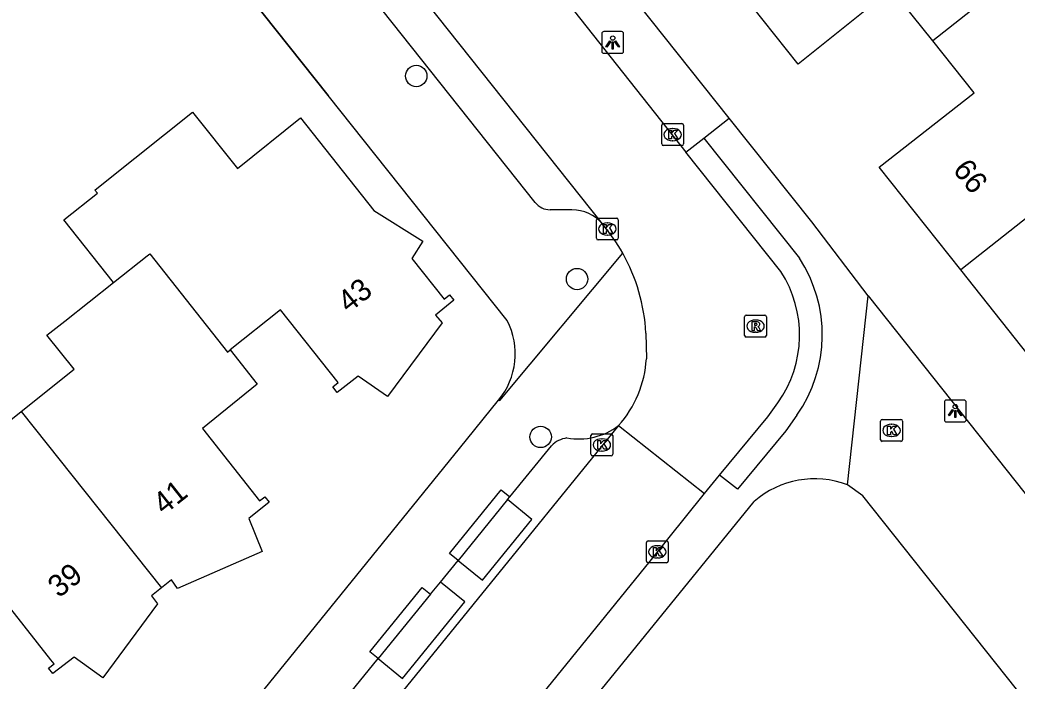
# Model space of a CAD drawing. Extents: x 157321 to 158827, y 386650 to 388532.
# Drawn here: x 157807.56 to 157853.16, y 387398.91 to 387429.15 of the extents above; entities that cross this region are included whole.
import ezdxf

# ---------------------------------------------------------------- set-up
doc = ezdxf.new("R2010")
doc.units = 0
for name, color, linetype in [('IMGEO_Boom', 7, 'Continuous'), ('IMGEO_Kolk', 7, 'Continuous'), ('IMGEO_Lichtpunt', 7, 'Continuous'), ('IMGEO_Muur', 7, 'Continuous'), ('IMGEO_Pand', 7, 'Continuous'), ('IMGEO_Pand_nummerreeks', 7, 'Continuous'), ('IMGEO_Rijbaan_lokaal_open', 7, 'Continuous'), ('IMGEO_Rioolput', 7, 'Continuous'), ('IMGEO_Voetpad_open', 7, 'Continuous')]:
    doc.layers.add(name, color=color, linetype=linetype)

msp = doc.modelspace()

# ---------------------------------------------------------------- linework, layer by layer
at = {"layer": 'IMGEO_Boom'}
for centre in [(157825.685, 387426.585), (157833.038, 387417.298), (157831.374, 387410.08)]:
    msp.add_circle(centre, 0.489, dxfattribs=at)
at = {"layer": 'IMGEO_Kolk'}
for p, q in [((157836.984, 387424.405), (157837.836, 387424.405)), ((157836.909, 387423.479), (157836.909, 387424.331)), ((157837.397, 387424.185), (157837.422, 387424.185)), ((157837.91, 387424.331), (157837.91, 387423.479)), ((157837.42, 387423.625), (157837.395, 387423.625)), ((157837.836, 387423.405), (157836.984, 387423.405)), ((157833.925, 387419.161), (157833.925, 387420.013)), ((157834, 387420.087), (157834.852, 387420.087)), ((157834.413, 387419.867), (157834.438, 387419.867)), ((157834.926, 387420.013), (157834.926, 387419.161)), ((157834.852, 387419.087), (157834, 387419.087)), ((157834.436, 387419.307), (157834.411, 387419.307)), ((157846.92, 387409.951), (157846.92, 387410.803)), ((157846.995, 387410.877), (157847.847, 387410.877)), ((157847.921, 387410.803), (157847.921, 387409.951)), ((157847.408, 387410.657), (157847.433, 387410.657)), ((157833.673, 387409.287), (157833.673, 387410.139)), ((157833.748, 387410.213), (157834.6, 387410.213)), ((157834.161, 387409.993), (157834.186, 387409.993)), ((157834.674, 387410.139), (157834.674, 387409.287)), ((157847.847, 387409.877), (157846.995, 387409.877)), ((157847.431, 387410.097), (157847.406, 387410.097)), ((157834.184, 387409.433), (157834.159, 387409.433)), ((157834.6, 387409.213), (157833.748, 387409.213)), ((157836.209, 387404.396), (157836.209, 387405.248)), ((157836.284, 387405.322), (157837.136, 387405.322)), ((157837.21, 387405.248), (157837.21, 387404.396)), ((157836.697, 387405.102), (157836.722, 387405.102)), ((157837.136, 387404.322), (157836.284, 387404.322)), ((157836.72, 387404.542), (157836.695, 387404.542))]:
    msp.add_line(p, q, dxfattribs=at)
for points in [[(157836.984, 387424.405), (157837.836, 387424.405)], [(157836.909, 387423.479), (157836.909, 387424.331)], [(157837.23, 387424.105), (157837.353, 387424.105), (157837.353, 387423.954), (157837.483, 387424.105), (157837.647, 387424.105), (157837.501, 387423.954), (157837.654, 387423.705), (157837.502, 387423.705), (157837.417, 387423.869), (157837.353, 387423.802), (157837.353, 387423.705), (157837.23, 387423.705), (157837.23, 387424.105)], [(157837.91, 387424.331), (157837.91, 387423.479)], [(157837.836, 387423.405), (157836.984, 387423.405)], [(157833.925, 387419.161), (157833.925, 387420.013)], [(157834, 387420.087), (157834.852, 387420.087)], [(157834.926, 387420.013), (157834.926, 387419.161)], [(157834.246, 387419.787), (157834.369, 387419.787), (157834.369, 387419.636), (157834.499, 387419.787), (157834.663, 387419.787), (157834.517, 387419.636), (157834.67, 387419.387), (157834.518, 387419.387), (157834.433, 387419.551), (157834.369, 387419.484), (157834.369, 387419.387), (157834.246, 387419.387), (157834.246, 387419.787)], [(157834.852, 387419.087), (157834, 387419.087)], [(157846.92, 387409.951), (157846.92, 387410.803)], [(157846.995, 387410.877), (157847.847, 387410.877)], [(157847.921, 387410.803), (157847.921, 387409.951)], [(157847.241, 387410.577), (157847.364, 387410.577), (157847.364, 387410.426), (157847.494, 387410.577), (157847.658, 387410.577), (157847.512, 387410.426), (157847.665, 387410.177), (157847.513, 387410.177), (157847.428, 387410.341), (157847.364, 387410.274), (157847.364, 387410.177), (157847.241, 387410.177), (157847.241, 387410.577)], [(157833.673, 387409.287), (157833.673, 387410.139)], [(157833.748, 387410.213), (157834.6, 387410.213)], [(157833.994, 387409.913), (157834.117, 387409.913), (157834.117, 387409.762), (157834.247, 387409.913), (157834.411, 387409.913), (157834.265, 387409.762), (157834.418, 387409.513), (157834.266, 387409.513), (157834.181, 387409.677), (157834.117, 387409.61), (157834.117, 387409.513), (157833.994, 387409.513), (157833.994, 387409.913)], [(157834.674, 387410.139), (157834.674, 387409.287)], [(157847.847, 387409.877), (157846.995, 387409.877)], [(157834.6, 387409.213), (157833.748, 387409.213)], [(157836.209, 387404.396), (157836.209, 387405.248)], [(157836.284, 387405.322), (157837.136, 387405.322)], [(157837.21, 387405.248), (157837.21, 387404.396)], [(157836.53, 387405.022), (157836.653, 387405.022), (157836.653, 387404.871), (157836.783, 387405.022), (157836.947, 387405.022), (157836.801, 387404.871), (157836.954, 387404.622), (157836.802, 387404.622), (157836.717, 387404.786), (157836.653, 387404.719), (157836.653, 387404.622), (157836.53, 387404.622), (157836.53, 387405.022)], [(157837.136, 387404.322), (157836.284, 387404.322)]]:
    msp.add_lwpolyline(points, dxfattribs=at)
for centre, start, end in [((157836.986, 387424.329), 91.552, 178.448), ((157836.986, 387424.329), 91.552, 178.448), ((157837.834, 387424.329), 1.552, 88.448), ((157837.834, 387424.329), 1.552, 88.448), ((157836.986, 387423.481), 181.552, 268.448), ((157836.986, 387423.481), 181.552, 268.448), ((157837.834, 387423.481), 271.552, 358.448), ((157837.834, 387423.481), 271.552, 358.448), ((157834.002, 387420.011), 91.552, 178.448), ((157834.002, 387420.011), 91.552, 178.448), ((157834.85, 387420.011), 1.552, 88.448), ((157834.85, 387420.011), 1.552, 88.448), ((157834.002, 387419.163), 181.552, 268.448), ((157834.002, 387419.163), 181.552, 268.448), ((157834.85, 387419.163), 271.552, 358.448), ((157834.85, 387419.163), 271.552, 358.448), ((157846.997, 387410.801), 91.552, 178.448), ((157846.997, 387410.801), 91.552, 178.448), ((157847.845, 387410.801), 1.552, 88.448), ((157847.845, 387410.801), 1.552, 88.448), ((157833.75, 387410.137), 91.552, 178.448), ((157833.75, 387410.137), 91.552, 178.448), ((157834.598, 387410.137), 1.552, 88.448), ((157834.598, 387410.137), 1.552, 88.448), ((157846.997, 387409.953), 181.552, 268.448), ((157846.997, 387409.953), 181.552, 268.448), ((157847.845, 387409.953), 271.552, 358.448), ((157847.845, 387409.953), 271.552, 358.448), ((157833.75, 387409.289), 181.552, 268.448), ((157833.75, 387409.289), 181.552, 268.448), ((157834.598, 387409.289), 271.552, 358.448), ((157834.598, 387409.289), 271.552, 358.448), ((157836.286, 387405.246), 91.552, 178.448), ((157836.286, 387405.246), 91.552, 178.448), ((157837.134, 387405.246), 1.552, 88.448), ((157837.134, 387405.246), 1.552, 88.448), ((157836.286, 387404.398), 181.552, 268.448), ((157836.286, 387404.398), 181.552, 268.448), ((157837.134, 387404.398), 271.552, 358.448), ((157837.134, 387404.398), 271.552, 358.448)]:
    msp.add_arc(centre, 0.0765, start, end, dxfattribs=at)
for centre, major_axis, ratio, start_param, end_param in [((157837.396, 387423.905), (-0.387, 0.002), 0.722429, 4.712389, 7.853982), ((157837.421, 387423.905), (-0.39, 0.002), 0.717154, 1.570796, 4.712389), ((157834.412, 387419.587), (-0.387, 0.002), 0.722429, 4.712389, 7.853982), ((157834.437, 387419.587), (-0.39, 0.002), 0.717154, 1.570796, 4.712389), ((157847.407, 387410.377), (-0.387, 0.002), 0.722429, 4.712389, 7.853982), ((157847.432, 387410.377), (-0.39, 0.002), 0.717154, 1.570796, 4.712389), ((157834.16, 387409.713), (-0.387, 0.002), 0.722429, 4.712389, 7.853982), ((157834.185, 387409.713), (-0.39, 0.002), 0.717154, 1.570796, 4.712389), ((157836.696, 387404.822), (-0.387, 0.002), 0.722429, 4.712389, 7.853982), ((157836.721, 387404.822), (-0.39, 0.002), 0.717154, 1.570796, 4.712389)]:
    msp.add_ellipse(centre, major_axis=major_axis, ratio=ratio, start_param=start_param, end_param=end_param, dxfattribs=at)
at = {"layer": 'IMGEO_Lichtpunt'}
for p, q in [((157834.171, 387428.524), (157834.171, 387427.717)), ((157834.171, 387428.524), (157834.171, 387427.717)), ((157835.073, 387428.619), (157834.265, 387428.619)), ((157835.073, 387428.619), (157834.265, 387428.619)), ((157835.167, 387427.717), (157835.167, 387428.524)), ((157835.167, 387427.717), (157835.167, 387428.524)), ((157834.265, 387427.623), (157835.073, 387427.623)), ((157834.265, 387427.623), (157835.073, 387427.623)), ((157849.836, 387411.668), (157849.836, 387410.861)), ((157849.836, 387411.668), (157849.836, 387410.861)), ((157850.738, 387411.763), (157849.93, 387411.763)), ((157850.738, 387411.763), (157849.93, 387411.763)), ((157850.832, 387410.861), (157850.832, 387411.668)), ((157850.832, 387410.861), (157850.832, 387411.668)), ((157849.93, 387410.767), (157850.738, 387410.767)), ((157849.93, 387410.767), (157850.738, 387410.767))]:
    msp.add_line(p, q, dxfattribs=at)
for points in [[(157834.545, 387428.188), (157834.584, 387428.16), (157834.396, 387427.898), (157834.358, 387427.925), (157834.545, 387428.188)], [(157834.647, 387428.14), (157834.694, 387428.14), (157834.694, 387427.818), (157834.647, 387427.818), (157834.647, 387428.14)], [(157834.757, 387428.16), (157834.795, 387428.187), (157834.982, 387427.925), (157834.943, 387427.897), (157834.757, 387428.16)], [(157850.21, 387411.332), (157850.249, 387411.304), (157850.061, 387411.042), (157850.023, 387411.069), (157850.21, 387411.332)], [(157850.312, 387411.284), (157850.359, 387411.284), (157850.359, 387410.962), (157850.312, 387410.962), (157850.312, 387411.284)], [(157850.422, 387411.304), (157850.46, 387411.331), (157850.647, 387411.069), (157850.608, 387411.041), (157850.422, 387411.304)]]:
    msp.add_lwpolyline(points, dxfattribs=at)
for centre in [(157834.67, 387428.322), (157850.335, 387411.466)]:
    msp.add_circle(centre, 0.0994, dxfattribs=at)
for centre, start, end in [((157834.265, 387428.524), 90, 180), ((157834.265, 387428.524), 90, 180), ((157835.073, 387428.524), 0, 90), ((157835.073, 387428.524), 0, 90), ((157834.265, 387427.717), 180, 270), ((157834.265, 387427.717), 180, 270), ((157835.073, 387427.717), 270, 0), ((157835.073, 387427.717), 270, 360), ((157849.93, 387411.668), 90, 180), ((157849.93, 387411.668), 90, 180), ((157850.738, 387411.668), 0, 90), ((157850.738, 387411.668), 0, 90), ((157849.93, 387410.861), 180, 270), ((157849.93, 387410.861), 180, 270), ((157850.738, 387410.861), 270, 0), ((157850.738, 387410.861), 270, 360)]:
    msp.add_arc(centre, 0.0946, start, end, dxfattribs=at)
at = {"layer": 'IMGEO_Muur'}
msp.add_lwpolyline([(157811.017, 387439.083), (157821.666, 387425.688)], dxfattribs=at)
at = {"layer": 'IMGEO_Pand'}
for points in [[(157854.979, 387432.676), (157849.307, 387428.187)], [(157849.307, 387428.187), (157847.41, 387430.562), (157843.144, 387427.129), (157839.411, 387431.832)], [(157850.582, 387417.726), (157846.859, 387422.419), (157851.199, 387425.818), (157849.307, 387428.187)], [(157811.845, 387417.145), (157809.573, 387420.006), (157811.104, 387421.226), (157810.989, 387421.37), (157811.544, 387421.813), (157815.453, 387424.929), (157817.509, 387422.361), (157820.389, 387424.666), (157823.749, 387420.429), (157825.982, 387419.026), (157825.487, 387418.238), (157826.959, 387416.382), (157827.205, 387416.577), (157827.402, 387416.328), (157826.573, 387415.652), (157826.878, 387415.299), (157824.364, 387411.921), (157823.03, 387412.85), (157822.066, 387412.117), (157821.867, 387412.368), (157822.118, 387412.567), (157819.481, 387415.888), (157817.17, 387414.054)], [(157858.965, 387424.329), (157850.582, 387417.726)], [(157811.845, 387417.145), (157813.38, 387418.36), (157813.498, 387418.453), (157817.053, 387413.961), (157817.17, 387414.054)], [(157860.457, 387414.083), (157858.595, 387416.474), (157854.309, 387413.027), (157850.582, 387417.726)], [(157807.619, 387411.241), (157810.044, 387413.172), (157808.8, 387414.734), (157809.615, 387415.38), (157811.845, 387417.145)], [(157817.17, 387414.054), (157818.414, 387412.487), (157815.905, 387410.462), (157818.518, 387407.155), (157818.77, 387407.345), (157818.96, 387407.095), (157818.037, 387406.343), (157818.641, 387404.833), (157814.77, 387403.147), (157814.497, 387403.549), (157814.036, 387403.182)], [(157802.299, 387403.379), (157799.818, 387406.513), (157802.304, 387408.463), (157803.013, 387407.572), (157807.619, 387411.241)], [(157807.619, 387411.241), (157814.036, 387403.182)], [(157814.036, 387403.182), (157813.574, 387402.814), (157813.862, 387402.445), (157811.35, 387399.063), (157810.037, 387400.008), (157809.073, 387399.258), (157808.877, 387399.506), (157809.125, 387399.702), (157808.977, 387399.889), (157806.525, 387402.989), (157804.2, 387401.149)]]:
    msp.add_lwpolyline(points, dxfattribs=at)
at = {"layer": 'IMGEO_Rijbaan_lokaal_open'}
for points in [[(157798.966, 387464.127), (157834.194, 387419.818)], [(157830.601, 387432.471), (157838.017, 387423.103)], [(157842.362, 387417.645), (157838.017, 387423.103)], [(157845.399, 387407.886), (157846.356, 387416.537)], [(157846.356, 387416.537), (157866.597, 387391.046)], [(157836.186, 387414.827), (157836.208, 387413.654)], [(157839.552, 387408.333), (157841.764, 387410.994), (157842.223, 387411.644)], [(157834.935, 387410.595), (157781.63, 387344.993)], [(157834.935, 387410.595), (157838.87, 387407.488)], [(157838.87, 387407.488), (157839.552, 387408.333)], [(157853.14, 387398.544), (157846.107, 387407.382), (157845.399, 387407.886)], [(157824.279, 387389.477), (157836.376, 387404.4), (157838.87, 387407.488)]]:
    msp.add_lwpolyline(points, dxfattribs=at)
for centre, radius, start, end in [((157827.748, 387414.319), 8.473, 29.4525, 40.468), ((157827.848, 387414.393), 8.349, 2.9768, 29.3438), ((157837.862, 387414.747), 5.352, 324.5628, 32.7834), ((157831.191, 387413.948), 5.026, 318.1595, 356.6513)]:
    msp.add_arc(centre, radius, start, end, dxfattribs=at)
at = {"layer": 'IMGEO_Rioolput'}
for p, q in [((157840.699, 387414.72), (157840.699, 387415.572)), ((157840.774, 387415.646), (157841.626, 387415.646)), ((157841.187, 387415.426), (157841.212, 387415.426)), ((157841.7, 387415.572), (157841.7, 387414.72)), ((157841.21, 387414.866), (157841.185, 387414.866)), ((157841.626, 387414.646), (157840.774, 387414.646))]:
    msp.add_line(p, q, dxfattribs=at)
for points in [[(157840.699, 387414.72), (157840.699, 387415.572)], [(157840.774, 387415.646), (157841.626, 387415.646)], [(157841.288, 387415.344), (157841.036, 387415.346), (157841.036, 387414.946)], [(157841.214, 387415.265), (157841.16, 387415.265), (157841.16, 387415.184)], [(157841.7, 387415.572), (157841.7, 387414.72)], [(157841.036, 387414.946), (157841.16, 387414.946), (157841.16, 387415.108), (157841.171, 387415.108)], [(157841.16, 387415.184), (157841.212, 387415.184)], [(157841.218, 387415.079), (157841.289, 387414.946), (157841.429, 387414.946), (157841.364, 387415.072)], [(157841.626, 387414.646), (157840.774, 387414.646)]]:
    msp.add_lwpolyline(points, dxfattribs=at)
for centre, radius, start, end in [((157840.776, 387415.57), 0.0765, 91.552, 178.448), ((157840.776, 387415.57), 0.0765, 91.552, 178.448), ((157841.22, 387415.169), 0.0964, 77.0061, 93.1865), ((157841.234, 387415.226), 0.0378, 276.6634, 79.6772), ((157841.287, 387415.234), 0.109, 350.3612, 89.416), ((157841.624, 387415.57), 0.0765, 1.552, 88.448), ((157841.624, 387415.57), 0.0765, 1.552, 88.448), ((157841.17, 387415.055), 0.0533, 26.0293, 88.6989), ((157841.196, 387415.373), 0.19, 274.7715, 282.9687), ((157841.285, 387415.234), 0.112, 277.5842, 350.9817), ((157841.269, 387415.019), 0.108, 29.5134, 73.7905), ((157840.776, 387414.722), 0.0765, 181.552, 268.448), ((157840.776, 387414.722), 0.0765, 181.552, 268.448), ((157841.624, 387414.722), 0.0765, 271.552, 358.448), ((157841.624, 387414.722), 0.0765, 271.552, 358.448)]:
    msp.add_arc(centre, radius, start, end, dxfattribs=at)
for centre, major_axis, ratio, start_param, end_param in [((157841.186, 387415.146), (-0.387, 0.002), 0.722429, 4.712389, 7.853982), ((157841.211, 387415.146), (-0.39, 0.002), 0.717154, 1.570796, 4.712389)]:
    msp.add_ellipse(centre, major_axis=major_axis, ratio=ratio, start_param=start_param, end_param=end_param, dxfattribs=at)
at = {"layer": 'IMGEO_Voetpad_open'}
for points in [[(157839.999, 387424.65), (157798.908, 387476.281)], [(157829.84, 387415.407), (157821.666, 387425.688), (157811.017, 387439.083), (157801.273, 387451.34), (157792.621, 387462.222)], [(157831.13, 387420.795), (157799.299, 387460.867)], [(157838.843, 387423.735), (157839.999, 387424.65)], [(157846.356, 387416.537), (157843.768, 387419.915), (157839.999, 387424.65)], [(157838.017, 387423.103), (157838.843, 387423.735)], [(157838.843, 387423.735), (157843.207, 387418.254)], [(157832.807, 387420.461), (157831.808, 387420.468)], [(157829.446, 387411.753), (157829.513, 387411.751), (157835.126, 387418.485)], [(157773.183, 387342.487), (157810.054, 387387.828), (157827.659, 387409.542), (157829.446, 387411.753)], [(157843.096, 387411.078), (157842.59, 387410.361), (157840.374, 387407.695), (157839.552, 387408.333)], [(157829.965, 387407.341), (157831.867, 387409.671)], [(157827.603, 387404.433), (157827.213, 387404.749), (157829.576, 387407.657), (157829.965, 387407.341)], [(157829.858, 387407.21), (157827.603, 387404.433)], [(157827.603, 387404.433), (157828.711, 387403.533), (157830.967, 387406.309), (157829.858, 387407.21)], [(157829.858, 387407.21), (157829.965, 387407.341)], [(157832.757, 387396.804), (157841.134, 387407.129)], [(157826.793, 387403.436), (157827.603, 387404.433)], [(157823.951, 387399.938), (157825.059, 387399.038), (157827.901, 387402.536), (157826.793, 387403.436)], [(157826.342, 387402.881), (157826.793, 387403.436)], [(157823.951, 387399.938), (157823.569, 387400.247), (157825.954, 387403.195), (157826.342, 387402.881)], [(157826.342, 387402.881), (157823.951, 387399.938)], [(157816.386, 387390.627), (157823.951, 387399.938)]]:
    msp.add_lwpolyline(points, dxfattribs=at)
for centre, radius, start, end in [((157831.799, 387421.316), 0.848, 217.8987, 270.6052), ((157832.834, 387418.702), 1.76, 39.379, 90.877), ((157837.864, 387414.748), 6.39, 324.9521, 33.2755), ((157826.889, 387413.877), 3.324, 320.283, 27.4085), ((157833.11, 387413.009), 3.026, 259.8579, 307.0913), ((157832.732, 387408.842), 1.198, 97.4279, 136.2175), ((157843.899, 387403.945), 4.217, 69.1604, 130.969)]:
    msp.add_arc(centre, radius, start, end, dxfattribs=at)

# ---------------------------------------------------------------- texts
at = {"layer": 'IMGEO_Pand_nummerreeks'}
for s, rotation, p in [('66', 308.4224, (157850.183, 387422.284)), ('43', 38.3366, (157822.59, 387415.715)), ('41', 38.285, (157814.146, 387406.481)), ('39', 38.3317, (157809.344, 387402.684))]:
    msp.add_text(s, height=1, rotation=rotation, dxfattribs=at).set_placement(p)

doc.saveas('drawing.dxf')
